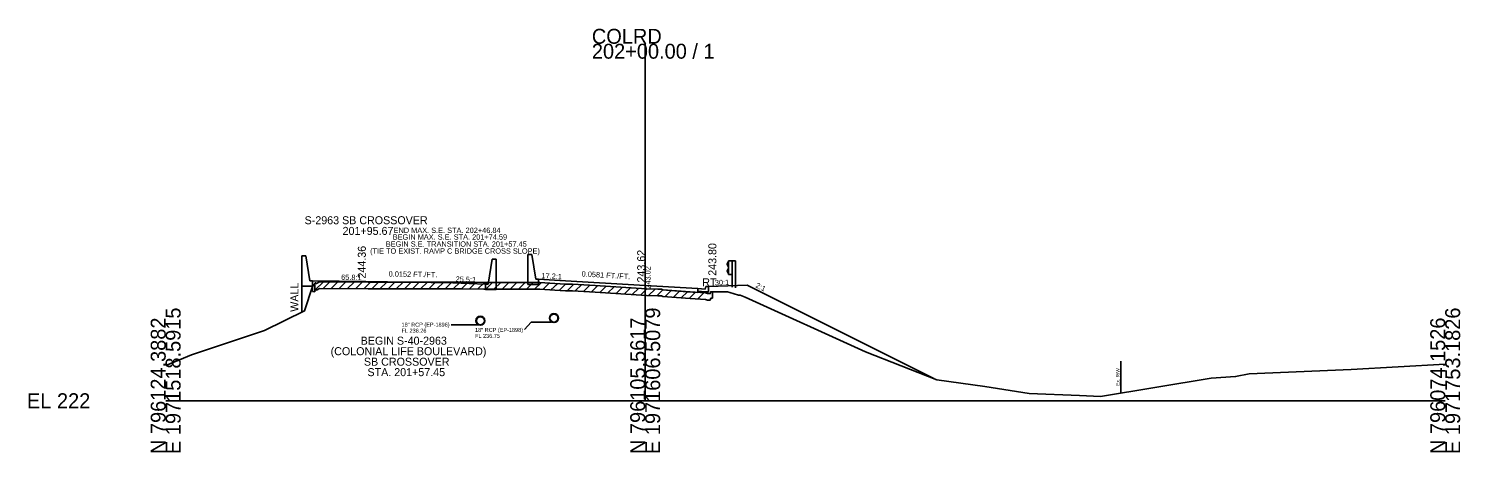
# Model space of a CAD drawing. Extents: x -26 to 1971520, y -10 to 796285.
# Drawn here: x 1274.3 to 1542.7, y -9.7 to 69.8 of the extents above; entities that cross this region are included whole.
import ezdxf

# ---------------------------------------------------------------- set-up
doc = ezdxf.new("R2010")
doc.units = 0
for name, color, linetype in [('RD_GPK_XS_Cell', 7, 'Continuous'), ('RD_XS_Base', 7, 'Continuous'), ('RD_XS_CurbBase', 7, 'Continuous'), ('RD_XS_CurbTop', 7, 'Continuous'), ('RD_XS_ExGround', 7, 'Continuous'), ('RD_XS_ExPaveRet', 7, 'Continuous'), ('RD_XS_ExRW', 7, 'Continuous'), ('RD_XS_GR', 7, 'Continuous'), ('RD_XS_MedBWall', 7, 'Continuous'), ('RD_XS_Misc_Line', 7, 'Continuous'), ('RD_XS_Pave', 7, 'Continuous'), ('RD_XS_PaveOvlay', 7, 'Continuous'), ('RD_XS_PaveShd', 7, 'Continuous'), ('RD_XS_Pipe', 7, 'Continuous'), ('RD_XS_TieSlope', 7, 'Continuous'), ('RD_XS_TX_Elev_EX', 7, 'Continuous'), ('RD_XS_TX_Elev_PR', 7, 'Continuous'), ('RD_XS_TX_MkPT', 7, 'Continuous'), ('RD_XS_TX_Notes', 7, 'Continuous'), ('RD_XS_TX_Slope', 7, 'Continuous'), ('RD_XS_TX_Station', 7, 'Continuous'), ('RD_XS_TX_TOC', 7, 'Continuous')]:
    doc.layers.add(name, color=color, linetype=linetype)

msp = doc.modelspace()

# ---------------------------------------------------------------- linework, layer by layer
at = {"layer": 'RD_GPK_XS_Cell'}
for p, q in [((1389.91, 0), (1389.91, 66.97)), ((1300, 0), (1389.91, 0)), ((1389.91, 0), (1539.91, 0))]:
    msp.add_line(p, q, dxfattribs=at)
at = {"layer": 'RD_XS_Base'}
for p, q in [((1327.53, 20.47), (1327.53, 22.51)), ((1327.97, 20.46), (1327.53, 20.47)), ((1399.75, 21.03), (1399.75, 21.05)), ((1399.75, 20.53), (1399.75, 21.03)), ((1399.75, 20.53), (1399.75, 20.3))]:
    msp.add_line(p, q, dxfattribs=at)
at = {"layer": 'RD_XS_CurbBase'}
for p, q in [((1401.17, 20.44), (1399.75, 20.53)), ((1401.75, 20.44), (1401.17, 20.44)), ((1401.75, 21.44), (1401.75, 20.44))]:
    msp.add_line(p, q, dxfattribs=at)
at = {"layer": 'RD_XS_CurbTop'}
for p, q in [((1399.75, 21.03), (1401.17, 20.95)), ((1401.17, 20.95), (1401.25, 21.44)), ((1401.25, 21.44), (1401.75, 21.44))]:
    msp.add_line(p, q, dxfattribs=at)
at = {"layer": 'RD_XS_ExGround'}
msp.add_lwpolyline([(1300, 6.62), (1304.86, 8.64), (1318.54, 13.2), (1326.06, 16.87), (1327.56, 21.4), (1328.09, 22.14), (1328.27, 21.97), (1328.82, 22.32), (1337.96, 22.24), (1338.89, 22.25), (1342.09, 22.25), (1355.71, 22.27), (1359.65, 22.2), (1360.92, 22.18), (1368.13, 22.15), (1370.18, 22.15), (1372.96, 21.99), (1374.99, 21.87), (1376.3, 21.88), (1380.51, 21.63), (1390.17, 21), (1392.3, 20.93), (1392.94, 20.9), (1393.2, 20.79), (1398.36, 20.4), (1401.19, 20.22), (1401.61, 20.12), (1402.1, 20.1), (1402.21, 20.46), (1405.35, 20.46), (1405.76, 20.33), (1407.42, 19.83), (1407.73, 19.81), (1408.66, 19.4), (1431.23, 9.18), (1444.62, 3.94), (1453.57, 2.67), (1461.9, 1.35), (1471.34, 0.95), (1475.3, 0.79), (1496.05, 4.22), (1500.61, 4.54), (1503.18, 5.04), (1522.28, 5.88), (1539.91, 6.88)], dxfattribs=at)
at = {"layer": 'RD_XS_ExPaveRet'}
for p, q in [((1327.97, 20.73), (1327.97, 21.98)), ((1327.97, 20.73), (1328.09, 20.89)), ((1328.09, 20.89), (1328.27, 20.72)), ((1328.27, 20.72), (1328.82, 21.07)), ((1328.82, 21.07), (1337.96, 20.99)), ((1337.96, 20.99), (1338.89, 21)), ((1338.89, 21), (1342.09, 21)), ((1342.09, 21), (1355.71, 21.02)), ((1355.71, 21.02), (1359.65, 20.95)), ((1359.65, 20.95), (1360.92, 20.93)), ((1360.92, 20.93), (1368.13, 20.9)), ((1368.13, 20.9), (1370.18, 20.9)), ((1370.18, 20.9), (1372.96, 20.74)), ((1372.96, 20.74), (1374.99, 20.62)), ((1374.99, 20.62), (1376.3, 20.63)), ((1376.3, 20.63), (1380.51, 20.38)), ((1380.51, 20.38), (1390.17, 19.75)), ((1390.17, 19.75), (1392.3, 19.68)), ((1392.3, 19.68), (1392.94, 19.65)), ((1392.94, 19.65), (1393.2, 19.54)), ((1393.2, 19.54), (1398.36, 19.15)), ((1398.36, 19.15), (1401.19, 18.97)), ((1401.19, 18.97), (1401.61, 18.87)), ((1401.61, 18.87), (1402.1, 18.85)), ((1402.1, 18.85), (1402.21, 19.21)), ((1402.21, 19.21), (1402.51, 19.21)), ((1402.51, 20.46), (1402.51, 19.21))]:
    msp.add_line(p, q, dxfattribs=at)
at = {"layer": 'RD_XS_ExRW'}
msp.add_line((1479.1, 7.42), (1479.1, 1.42), dxfattribs=at)
at = {"layer": 'RD_XS_GR'}
for p, q in [((1405.52, 26.1), (1405.25, 25.66)), ((1405.25, 25.66), (1405.25, 25.55)), ((1405.25, 25.55), (1405.52, 25.11)), ((1405.25, 24.4), (1405.52, 24.84)), ((1405.25, 24.29), (1405.25, 24.4)), ((1405.52, 23.85), (1405.25, 24.29)), ((1405.52, 26.26), (1406.19, 26.26)), ((1405.52, 23.69), (1405.52, 26.26)), ((1406.19, 26.26), (1406.86, 26.26)), ((1406.19, 26.26), (1406.19, 21.31)), ((1406.86, 26.26), (1406.86, 21.2)), ((1405.52, 23.69), (1406.19, 23.69))]:
    msp.add_line(p, q, dxfattribs=at)
at = {"layer": 'RD_XS_MedBWall'}
for p, q in [((1326.28, 27.18), (1325.53, 27.18)), ((1325.53, 27.18), (1325.53, 21.51)), ((1327.03, 22.51), (1326.28, 27.18)), ((1368.66, 27.45), (1367.91, 27.45)), ((1367.91, 27.45), (1367.91, 21.78)), ((1369.41, 22.78), (1368.66, 27.45)), ((1360.46, 21.87), (1361.21, 26.53)), ((1361.21, 26.53), (1361.96, 26.53)), ((1361.96, 26.53), (1361.96, 20.87)), ((1325.53, 16.62), (1325.53, 21.51)), ((1325.53, 21.51), (1327.53, 21.51)), ((1327.53, 22.51), (1327.03, 22.51)), ((1327.53, 21.51), (1327.53, 22.51)), ((1359.96, 20.87), (1359.96, 21.87)), ((1359.96, 21.87), (1360.46, 21.87)), ((1367.91, 21.78), (1369.91, 21.78)), ((1369.91, 22.78), (1369.41, 22.78)), ((1369.91, 21.78), (1369.91, 22.78)), ((1361.96, 20.87), (1359.96, 20.87))]:
    msp.add_line(p, q, dxfattribs=at)
at = {"layer": 'RD_XS_Misc_Line'}
for p, q in [((1327.97, 20.73), (1329.59, 22.32)), ((1329.5, 21.07), (1330.76, 22.31)), ((1331.03, 21.05), (1332.29, 22.29)), ((1332.55, 21.04), (1333.81, 22.28)), ((1334.08, 21.03), (1335.34, 22.27)), ((1335.6, 21.01), (1336.87, 22.25)), ((1337.13, 21), (1338.4, 22.25)), ((1338.66, 21), (1339.93, 22.25)), ((1340.18, 21), (1341.45, 22.25)), ((1341.71, 21), (1342.98, 22.25)), ((1343.24, 21.01), (1344.51, 22.26)), ((1344.76, 21.01), (1346.03, 22.26)), ((1346.29, 21.01), (1347.56, 22.26)), ((1347.81, 21.01), (1349.09, 22.26)), ((1349.34, 21.01), (1350.61, 22.26)), ((1350.87, 21.01), (1352.14, 22.26)), ((1352.39, 21.01), (1353.67, 22.26)), ((1353.92, 21.01), (1355.19, 22.27)), ((1355.45, 21.02), (1356.7, 22.25)), ((1356.97, 20.99), (1358.22, 22.22)), ((1358.5, 20.97), (1359.75, 22.19)), ((1360.02, 20.94), (1361.28, 22.18)), ((1361.55, 20.93), (1362.82, 22.17)), ((1363.08, 20.92), (1364.34, 22.17)), ((1364.6, 20.92), (1365.87, 22.16)), ((1366.13, 20.91), (1367.4, 22.16)), ((1367.65, 20.91), (1368.92, 22.15)), ((1369.18, 20.9), (1370.43, 22.13)), ((1370.71, 20.87), (1371.91, 22.05)), ((1372.23, 20.78), (1373.44, 21.96)), ((1373.76, 20.69), (1374.96, 21.87)), ((1375.29, 20.62), (1376.55, 21.87)), ((1376.81, 20.6), (1378.01, 21.78)), ((1378.34, 20.51), (1379.54, 21.69)), ((1379.86, 20.42), (1381.06, 21.59)), ((1381.39, 20.32), (1382.58, 21.49)), ((1382.92, 20.22), (1384.11, 21.39)), ((1384.44, 20.12), (1385.64, 21.3)), ((1385.97, 20.02), (1387.16, 21.2)), ((1387.49, 19.92), (1388.69, 21.1)), ((1389.02, 19.83), (1390.22, 21)), ((1390.55, 19.74), (1391.78, 20.95)), ((1392.07, 19.69), (1393.19, 20.79)), ((1393.6, 19.51), (1394.78, 20.67)), ((1395.13, 19.39), (1396.31, 20.55)), ((1396.65, 19.28), (1397.83, 20.44)), ((1398.18, 19.16), (1399.37, 20.34)), ((1399.7, 19.06), (1400.9, 20.24))]:
    msp.add_line(p, q, dxfattribs=at)
at = {"layer": 'RD_XS_Pave'}
for p, q in [((1337.53, 22.36), (1353.87, 22.11)), ((1389.91, 21.62), (1373.91, 22.55)), ((1389.91, 21.62), (1399.75, 21.05))]:
    msp.add_line(p, q, dxfattribs=at)
at = {"layer": 'RD_XS_PaveOvlay'}
for p, q in [((1327.97, 21.98), (1328.09, 22.14)), ((1327.97, 21.98), (1327.97, 20.46)), ((1328.09, 22.14), (1328.27, 21.97)), ((1328.27, 21.97), (1328.82, 22.32)), ((1328.82, 22.32), (1337.96, 22.24)), ((1337.96, 22.24), (1338.89, 22.25)), ((1338.89, 22.25), (1342.09, 22.25)), ((1342.09, 22.25), (1355.71, 22.27)), ((1355.71, 22.27), (1357.96, 22.23)), ((1369.91, 22.15), (1370.18, 22.15)), ((1370.18, 22.15), (1372.96, 21.99)), ((1372.96, 21.99), (1374.99, 21.87)), ((1374.99, 21.87), (1376.3, 21.88)), ((1376.3, 21.88), (1380.51, 21.63)), ((1380.51, 21.63), (1390.17, 21)), ((1390.17, 21), (1392.3, 20.93)), ((1392.3, 20.93), (1392.94, 20.9)), ((1392.94, 20.9), (1393.2, 20.79)), ((1393.2, 20.79), (1393.9, 20.73)), ((1397.83, 20.44), (1393.9, 20.73)), ((1399.75, 20.31), (1397.83, 20.44))]:
    msp.add_line(p, q, dxfattribs=at)
at = {"layer": 'RD_XS_PaveShd'}
for p, q in [((1337.53, 22.36), (1327.53, 22.51)), ((1353.87, 22.11), (1359.96, 21.87)), ((1360.46, 21.87), (1359.96, 21.87)), ((1360.51, 22.19), (1360.46, 21.87)), ((1360.92, 22.18), (1360.51, 22.19)), ((1363.17, 22.17), (1360.92, 22.18)), ((1369.91, 22.13), (1363.17, 22.16)), ((1373.91, 22.55), (1369.91, 22.78)), ((1369.91, 22.78), (1369.91, 22.13))]:
    msp.add_line(p, q, dxfattribs=at)
at = {"layer": 'RD_XS_Pipe'}
for p, q in [((1358.51, 14.26), (1353.51, 14.26)), ((1368.51, 14.75), (1367.29, 13.39)), ((1372.31, 14.75), (1368.51, 14.75))]:
    msp.add_line(p, q, dxfattribs=at)
for centre, radius in [((1372.81, 15.5), 0.85), ((1372.81, 15.5), 0.75), ((1359.01, 15.01), 0.85), ((1359.01, 15.01), 0.75)]:
    msp.add_circle(centre, radius, dxfattribs=at)
at = {"layer": 'RD_XS_TieSlope'}
for p in [(1401.75, 21.44), (1444.05, 4.16)]:
    msp.add_line(p, (1409, 21.69), dxfattribs=at)

# ---------------------------------------------------------------- texts
at = {"layer": 'RD_GPK_XS_Cell'}
for s, p in [('COLRD', (1379.91, 66.97)), ('202+00.00 / 1', (1379.91, 64.17)), ('EL 222', (1274, -1.4))]:
    msp.add_text(s, height=2.8, dxfattribs=at).set_placement(p)
for s, p in [('E 1971518.5915', (1302.8, -10)), ('E 1971606.5079', (1392.71, -10)), ('E 1971753.1826', (1542.71, -10)), ('N 796124.3882', (1300, -10)), ('N 796105.5617', (1389.91, -10)), ('N 796074.1526', (1539.91, -10))]:
    msp.add_text(s, height=2.8, rotation=90, dxfattribs=at).set_placement(p)
at = {"layer": 'RD_XS_ExRW'}
msp.add_text('Ex. R/W ', height=0.65, rotation=90, dxfattribs=at).set_placement((1478.85, 2.81))
at = {"layer": 'RD_XS_Pipe'}
for s, p in [('18" RCP (EP-1896)', (1344.23, 13.89)), ('FL 236.26', (1344.23, 12.76)), ('18" RCP (EP-1898)', (1358.01, 12.91)), ('FL 236.75', (1358.01, 11.79))]:
    msp.add_text(s, height=0.75, dxfattribs=at).set_placement(p)
at = {"layer": 'RD_XS_TX_Elev_EX'}
msp.add_text('243.02', height=1, rotation=90, dxfattribs=at).set_placement((1390.91, 21.02))
at = {"layer": 'RD_XS_TX_Elev_PR'}
for s, p in [(' 244.36', (1337.53, 22.36)), (' 243.62', (1389.91, 21.62))]:
    msp.add_text(s, height=1.5, rotation=90, dxfattribs=at).set_placement(p)
at = {"layer": 'RD_XS_TX_MkPT'}
msp.add_text('RT', height=1.5, dxfattribs=at).set_placement((1400.61, 21.46))
at = {"layer": 'RD_XS_TX_Notes'}
for s, height, p in [('END MAX. S.E. STA. 202+46.84', 1, (1342.73, 31.47)), ('BEGIN S.E. TRANSITION STA. 201+57.45', 1, (1341.27, 28.9)), ('BEGIN MAX. S.E. STA. 201+74.59', 1, (1342.57, 30.22)), ('(TIE TO EXIST. RAMP C BRIDGE CROSS SLOPE)', 1, (1338.33, 27.59)), ('BEGIN S-40-2963', 1.5, (1336.56, 10.51)), ('(COLONIAL LIFE BOULEVARD)', 1.5, (1330.93, 8.54)), ('SB CROSSOVER', 1.5, (1337.17, 6.57)), ('STA. 201+57.45', 1.5, (1337.84, 4.61))]:
    msp.add_text(s, height=height, dxfattribs=at).set_placement(p)
msp.add_text('WALL', height=1.5, rotation=90, dxfattribs=at).set_placement((1324.9, 16.68))
at = {"layer": 'RD_XS_TX_Slope'}
for s, rotation, p in [('0.0152 FT./FT.', 359.1289, (1341.8, 23.29)), ('0.0581 FT./FT.', 356.6749, (1377.97, 23.32)), ('65.8:1', 359.1289, (1332.89, 22.68)), ('25.5:1', 357.757, (1354.35, 22.34)), ('17.2:1', 356.6749, (1370.44, 23)), ('30:1', 1.1458, (1402.97, 21.66)), ('2:1', 333.4349, (1410.5, 21.33))]:
    msp.add_text(s, height=1, rotation=rotation, dxfattribs=at).set_placement(p)
at = {"layer": 'RD_XS_TX_Station'}
for s, p in [('S-2963 SB CROSSOVER', (1326.05, 33.11)), ('201+95.67', (1333.17, 31.11))]:
    msp.add_text(s, height=1.5, dxfattribs=at).set_placement(p)
at = {"layer": 'RD_XS_TX_TOC'}
msp.add_text('243.80', height=1.5, rotation=90, dxfattribs=at).set_placement((1403.25, 23.44))

doc.saveas('drawing.dxf')
